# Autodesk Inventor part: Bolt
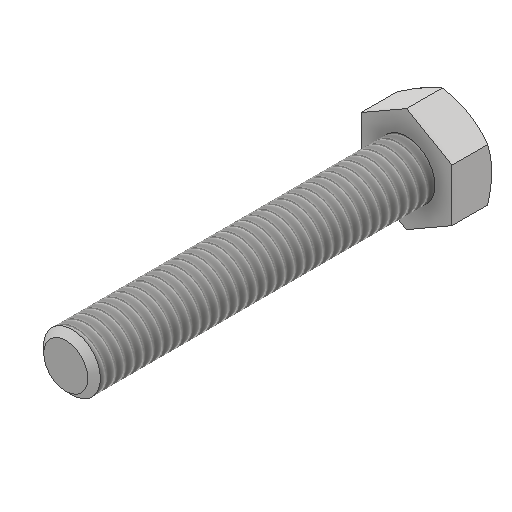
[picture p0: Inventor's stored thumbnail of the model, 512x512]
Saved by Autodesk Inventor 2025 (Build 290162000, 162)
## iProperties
Created: 2016-05
Part Number: Bolt
Material: Generic
Document SubType Name: Modeling
Designer: CADCIM
Density: 1 g/cm^3
Appearance: Default
Author: CADCIM
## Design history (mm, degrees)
sketch "Sketch1"
  geometry: L1 (3.604, -2.072)-(0.007, -4.157); L2 (0.007, -4.157)-(-3.596, -2.085); L3 (-3.596, -2.085)-(-3.604, 2.072); L4 (-3.604, 2.072)-(-0.007, 4.157); L5 (-0.007, 4.157)-(3.596, 2.085); L6 (3.596, 2.085)-(3.604, -2.072); 2 further points
  constraints: 12 end point, 1 coincident, 13 other
  dimensions: "d0" = 7.2 distance between parallel lines of L3 L6
extrude "Extrusion1" new body sketch "Sketch1" distance "d1" = 3.15; taper "d2" = 0 deg
sketch "Sketch2"
  geometry: C1 r 2.25 at (0, 0); 1 further point
  constraints: 1 centre point, 1 coincident
  dimensions: "d3" = 4.5 diameter of C1
extrude "Extrusion2" join sketch "Sketch2" distance "d4" = 27; taper "d5" = 0 deg
thread "Thread1" dims "d6" = 27, "d7" = 0
chamfer "Chamfer1" distance "d8" = 0.5; stored, may be unused: second distance "d9" = 2, angle "d10" = 45 deg
sketch "Sketch3"
  geometry: L1 (0.007, -4.157)-(3.604, -2.072) reference; C1 r 3.6 at (0, 0); 1 further point
  constraints: 1 centre point, 1 coincident, 1 tangent
extrude "Extrusion3" sketch "Sketch3" distance "d11" = 41; taper "d12" = 60 deg
body "Solid1"
